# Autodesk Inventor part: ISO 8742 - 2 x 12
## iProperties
Created: 2004-01
Part Number: ISO 8742 - 2 x 12
Material: Standard
Catalog Web Link: file:///C:/Programme/Autodesk/Inventor 5.3/Content/Din/index.htm?doNavigateId=DF1221BA-CB3D-11D4-A9FB-0080AD303E0A|0557BC68B16611D4BA6900C04F798F98|true
Description: Kerbstift
Document SubType Name: Standard Catalog Part
Standard: ISO 8742 - 2 x 12
Designer: Ulrich
Control State: 0
Master: False
Checked Out: False
Shininess: 20.0
Angle Display Precision: 2
Document Length Units: 11269
Document Angle Units: 11279
Document Time Units: 11290
Document Mass Units: 11283
Document Length Units Precision: 3
Document Angle Units Precision: 2
Compacted: True
KLASSIFIKATION: 31163206 un/spsc
HERSTELLER: DIN Normsystem
Density: 0.0
Volumn: 0.0
Area: 0.0
PropertySet Name: Model Information
Author: Ulrich
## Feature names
1. Basis1
